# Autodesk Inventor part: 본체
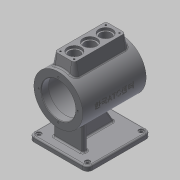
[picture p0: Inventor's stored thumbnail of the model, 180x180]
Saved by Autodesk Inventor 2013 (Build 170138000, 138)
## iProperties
Created: 2015-11
Part Number: 본체
Material: 일반
Document SubType Name: Modeling
Designer: mduedu
Density: 2.71 g/cm^3
Author: mduedu
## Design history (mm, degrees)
sketch "스케치2"
  geometry: C1 r 50 at (0, 0); 1 further point
  constraints: 1 centre point, 1 coincident
  dimensions: "d147" = 100 diameter of C1
extrude "돌출1" new body sketch "스케치2" stored distance "d12" = 130; taper "d13" = 0 deg
feature "쉘1" dims "d31" = 15, "d32" = 6, "d33" = 15
sketch "스케치5"
  geometry: C1 r 35 at (0, 0); 1 further point
  constraints: 1 centre point, 1 coincident
  dimensions: "d34" = 70 diameter of C1
extrude "돌출3" cut sketch "스케치5" stored distance "d36" = 3; taper "d37" = 0 deg
node "작업 평면1"
sketch "스케치6"
  geometry: L1 (-65, -60)-(65, -60); L2 (65, -60)-(65, 60); L3 (65, 60)-(-65, 60); L4 (-65, 60)-(-65, -60); L5 (-65, -60)-(65, 60); L6 (65, -60)-(-65, 60); 1 further point
  constraints: 12 end point, 2 midpoint, 2 parallel, 1 horizontal, 1 perpendicular
  dimensions: "d41" = 120 distance of L3.end L1.start; "d43" = 130 distance of L2.end L3.end
extrude "돌출4" join sketch "스케치6" distance "d44" = 10; taper "d45" = 0 deg
sketch "스케치19"
  geometry: L1 (-45, 30)-(-35, 30); L2 (-35, 30)-(-35, -30); L3 (-35, -30)-(-45, -30); L4 (-45, -30)-(-45, 30); L5 (-65, 60)-(-65, -60) reference; 2 further points
  constraints: 8 end point, 2 parallel, 1 horizontal, 1 horizontal alignment, 1 midpoint, 1 perpendicular
  dimensions: "d150" = 20 distance between parallel lines of L4 L5; "d151" = 10 distance of L1.start L1.end; "d152" = 60 distance of L3.end L1.start
extrude "돌출9" join sketch "스케치19" stored distance "d153" = 10; taper "d154" = 0 deg
sketch "스케치20"
  geometry: L1 (65, 35)-(50, 35) reference; L2 (50, 35)-(50, 44) reference; L3 (50, 44)-(-50, 44) reference; L4 (-50, 44)-(-50, 35) reference; L5 (-50, 35)-(-65, 35) reference; L6 (-65, 35)-(-65, 50) reference; L7 (-65, 50)-(65, 50) reference; L8 (65, 50)-(65, 35) reference; L9 (50, -35)-(65, -35) reference; L10 (65, -35)-(65, -50) reference; L11 (65, -50)-(45, -50) reference; L12 (45, -50)-(45, -90) reference; L13 (45, -90)-(65, -90) reference; L14 (65, -90)-(65, -100) reference; L15 (65, -100)-(-65, -100) reference; L16 (-65, -100)-(-65, -90) reference; L17 (-65, -90)-(35, -90) reference; L18 (35, -90)-(35, -50) reference; L19 (35, -50)-(-65, -50) reference; L20 (-65, -50)-(-65, -35) reference; L21 (-65, -35)-(-50, -35) reference; L22 (-50, -35)-(-50, -44) reference; L23 (-50, -44)-(50, -44) reference; L24 (50, -44)-(50, -35) reference; L25 (-45, -90)-(-21.906, -50); 1 further point
  constraints: 2 end point, 2 point on line
  dimensions: "d155" = 20 distance from line of L25.start L16; "d156" = 120 deg angle of L25 L17
feature "리브2" sketch "스케치20" dims "d157" = 1, "d158" = 10, "d159" = 0, "d160" = 0, "d161" = 1, "d162" = 1
fillet "모깎기21" dims "d163" = 3
fillet "모깎기22" dims "d164" = 3
fillet "모깎기23" dims "d165" = 3
sketch "스케치21" dims "d166" = 80
  geometry: 3 further points
  constraints: 2 horizontal alignment, 1 coincident, 2 other
hole "구멍6" sketch "스케치21" at (40, 0) diameter "d168" = 3.242; stored, may be unused: countersink angle "d172" = 90 deg, drill point angle "d174" = 118 deg; dims "d169" = 9, "d170" = 4, "d171" = 2, "d173" = 11
node "작업 평면2"
sketch "스케치13"
  geometry: L1 (-52.5, -20)-(52.5, -20); L2 (52.5, -20)-(52.5, 20); L3 (52.5, 20)-(-52.5, 20); L4 (-52.5, 20)-(-52.5, -20); L5 (-52.5, -20)-(52.5, 20); L6 (52.5, -20)-(-52.5, 20); 1 further point
  constraints: 12 end point, 2 midpoint, 2 parallel, 1 horizontal, 1 perpendicular
  dimensions: "d93" = 105 distance of L2.end L3.end; "d95" = 40 distance of L1.end L2.end
extrude "돌출8" join sketch "스케치13" stored distance "d96" = 80; taper "d97" = 0 deg
fillet "모깎기15" dims "d98" = 5
feature "면 기울기1" dims angle "d178" = 10 deg
fillet "모깎기24" dims "d179" = 3
sketch "스케치14"
  geometry: L1 (-52.5, 15)-(-52.5, -15) reference; L2 (52.5, -15)-(52.5, 15) reference; L3 (-52.5, 0)-(52.5, 0); 4 further points
  constraints: 2 end point, 2 midpoint, 2 point on line, 1 coincident
  dimensions: "d100" = 32 distance of point (-32, 0) point (0, 0); "d102" = 32 distance of point (32, 0) point (0, 0) (derived)
hole "구멍3" sketch "스케치14" at (-32, 0), (0, 0), (32, 0) diameter "d103" = 22; stored, may be unused: countersink angle "d107" = 90 deg, drill point angle "d109" = 118 deg; dims "d104" = 8, "d105" = 28, "d106" = 5, "d108" = 10
sketch "스케치15"
  geometry: L1 (46.5, -14)-(-46.5, -14); L2 (-46.5, -14)-(-46.5, 14); L3 (-46.5, 14)-(46.5, 14); L4 (46.5, 14)-(46.5, -14); L5 (46.5, -14)-(-46.5, 14); L6 (-46.5, -14)-(46.5, 14); L7 (47.5, 20)-(-47.5, 20) reference; L8 (-52.5, 15)-(-52.5, -15) reference; 5 further points
  constraints: 12 end point, 4 coincident, 2 midpoint, 2 parallel, 1 horizontal, 1 perpendicular
  dimensions: "d110" = 6 distance between parallel lines of L3 L7; "d111" = 6 distance between parallel lines of L2 L8
hole "구멍4" sketch "스케치15" at (-46.5, 14), (46.5, 14), (46.5, -14), (-46.5, -14) diameter "d112" = 3.242; stored, may be unused: countersink angle "d116" = 90 deg, drill point angle "d118" = 118 deg; dims "d113" = 10, "d114" = 28, "d115" = 5, "d117" = 13
node "작업 평면3"
sketch "스케치22"
  geometry: 2 further points
  constraints: 1 coincident, 1 other
feature "엠보싱3" sketch "스케치22" dims "d32" = 6, "d181" = 0.5, "d182" = 0
chamfer "모따기2" distance "d183" = 1; stored, may be unused: second distance "d184" = 2, angle "d185" = 45 deg
fillet "모깎기25" dims "d186" = 10
sketch "스케치23"
  geometry: L1 (55, 60)-(-55, 60) reference; L2 (65, -50)-(65, 50) reference; L3 (-55, -60)-(55, -60) reference; L4 (-65, 50)-(-65, -50) reference; A1 r 10 centre (-55, 50) between (-55, 60) and (-65, 50) reference; A2 r 10 centre (55, 50) between (65, 50) and (55, 60) reference; A3 r 10 centre (55, -50) between (55, -60) and (65, -50) reference; A4 r 10 centre (-55, -50) between (-65, -50) and (-55, -60) reference; 1 further point
hole "구멍7" sketch "스케치23" at (-55, 50), (-55, -50), (55, -50), (55, 50) diameter "d187" = 6; stored, may be unused: countersink angle "d191" = 90 deg, drill point angle "d193" = 118 deg; dims "d188" = 9, "d189" = 10, "d190" = 2, "d192" = 11
fillet "모깎기26" dims "d194" = 3
node "솔리드1"
pattern_circular "원형 패턴2" dims angle "d176" = 360 deg
mirror "대칭5"
node "투영된 루프2"
node "절단 모서리 투영1"
